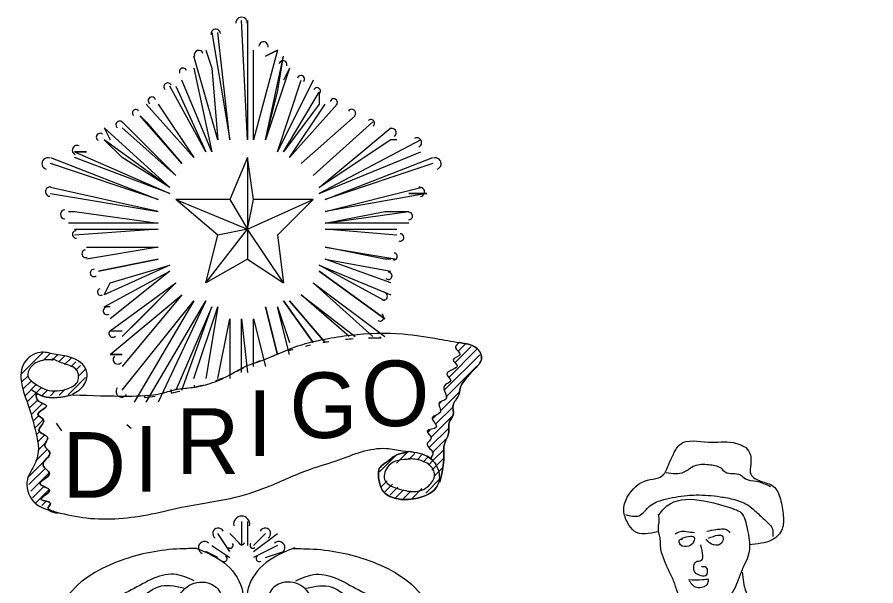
# Model space of a CAD drawing. Extents: x -1.5 to 32.9, y -63.9 to -9.8.
# Drawn here: x 14.803 to 15.935, y -13.417 to -12.666 of the extents above; entities that cross this region are included whole.
import ezdxf

# ---------------------------------------------------------------- set-up
doc = ezdxf.new("R2010")
doc.units = 0
doc.layers.add('BORDER', color=7, linetype='Continuous')

msp = doc.modelspace()

# ---------------------------------------------------------------- linework, layer by layer
at = {"layer": 'BORDER'}
for p, q in [((15.1066, -12.8281), (15.0987, -12.6706)), ((15.1066, -12.6706), (15.1066, -12.8281)), ((15.0593, -12.6864), (15.083, -12.8281)), ((15.083, -12.8281), (15.0672, -12.6864)), ((15.0515, -12.71), (15.0593, -12.7336)), ((15.1145, -12.8281), (15.1145, -12.71)), ((15.1302, -12.8281), (15.1538, -12.7179)), ((15.0357, -12.7336), (15.0593, -12.8439)), ((15.1617, -12.7336), (15.1302, -12.8281)), ((15.1617, -12.7336), (15.1538, -12.7494)), ((15.0593, -12.8439), (15.02, -12.7494)), ((15.1459, -12.8439), (15.1774, -12.7494)), ((15.0121, -12.7573), (15.0515, -12.8439)), ((15.1538, -12.8439), (15.2011, -12.7651)), ((15.02, -12.8596), (14.9648, -12.7966)), ((15.2483, -12.7966), (15.1774, -12.8596)), ((15.1932, -12.8754), (15.2719, -12.8045)), ((15.2719, -12.8045), (15.1932, -12.8754)), ((14.9176, -12.8124), (14.9255, -12.8281)), ((14.9176, -12.8124), (15.0042, -12.8911)), ((15.0121, -12.8754), (14.9412, -12.8124)), ((15.0042, -12.8911), (14.9176, -12.8281)), ((15.3349, -12.8281), (15.2011, -12.899)), ((15.3034, -12.8281), (15.2956, -12.8281)), ((14.8467, -12.8517), (14.9885, -12.9069)), ((15.0042, -12.899), (14.8782, -12.8517)), ((15.2011, -12.899), (15.3349, -12.8439)), ((15.2089, -12.9069), (15.3507, -12.8517)), ((14.9885, -12.9069), (14.8467, -12.8596)), ((15.3507, -12.8596), (15.2089, -12.9069)), ((14.9885, -12.9226), (14.8467, -12.8911)), ((15.2089, -12.9226), (15.3349, -12.8911)), ((14.8467, -12.899), (14.9885, -12.9226)), ((15.083, -12.9069), (15.1066, -12.9462)), ((15.1932, -12.9069), (15.1145, -12.9069)), ((14.8704, -12.9226), (14.8782, -12.9226)), ((15.2089, -12.9384), (15.3192, -12.9226)), ((15.3192, -12.9384), (15.2089, -12.9384)), ((15.3192, -12.9384), (15.3034, -12.9384)), ((14.9885, -12.9462), (14.8782, -12.9541)), ((14.8782, -12.9462), (14.9885, -12.9462)), ((15.0515, -13.0171), (15.0672, -12.9541)), ((15.2089, -12.9462), (15.3034, -12.9462)), ((14.894, -12.9699), (14.9885, -12.9699)), ((15.2089, -12.9699), (15.3034, -12.9856)), ((15.1066, -12.9856), (15.1538, -13.0171)), ((15.0042, -12.9935), (14.9176, -13.0328)), ((15.2877, -13.0407), (15.2011, -12.9935)), ((15.0042, -13.0014), (14.9255, -13.0643)), ((15.2011, -13.0014), (15.2877, -13.0643)), ((15.2877, -13.0643), (15.2011, -13.0014)), ((14.9255, -13.0801), (15.0121, -13.0171)), ((15.0121, -13.0171), (14.9412, -13.088)), ((15.02, -13.0328), (14.9412, -13.1273)), ((14.9412, -13.1588), (15.0357, -13.0407)), ((15.0357, -13.0407), (14.957, -13.1746)), ((15.1538, -13.0407), (15.1932, -13.0958)), ((15.1932, -13.0958), (15.1538, -13.0407)), ((15.1145, -13.0643), (15.1302, -13.1273)), ((15.1145, -13.1273), (15.1145, -13.0643)), ((14.9255, -13.0801), (14.9412, -13.0801)), ((15.3802, -13.1222), (15.4015, -13.101)), ((15.3839, -13.1074), (15.3934, -13.0979)), ((14.808, -13.1376), (14.8364, -13.1091)), ((14.8371, -13.1195), (14.8463, -13.1103)), ((14.8485, -13.1193), (14.8559, -13.1119)), ((14.858, -13.1209), (14.8651, -13.1138)), ((15.3668, -13.1579), (15.4128, -13.1119)), ((15.3719, -13.1417), (15.4095, -13.104)), ((14.8652, -13.1248), (14.8741, -13.116)), ((14.8732, -13.128), (14.8801, -13.1211)), ((14.8801, -13.1322), (14.8861, -13.1262)), ((14.8843, -13.1392), (14.8922, -13.1313)), ((15.3681, -13.1677), (15.4084, -13.1275)), ((14.809, -13.1476), (14.8167, -13.14)), ((14.8103, -13.1575), (14.8221, -13.1457)), ((14.8697, -13.1649), (14.8926, -13.142)), ((14.8131, -13.1659), (14.8278, -13.1511)), ((14.8158, -13.1742), (14.8347, -13.1553)), ((14.8351, -13.1661), (14.8427, -13.1585)), ((14.858, -13.1654), (14.8661, -13.1573)), ((14.8464, -13.1659), (14.8524, -13.1599)), ((15.3606, -13.1864), (15.3859, -13.161)), ((14.8186, -13.1826), (14.83, -13.1712)), ((14.8212, -13.1911), (14.8361, -13.1763)), ((15.354, -13.2041), (15.3776, -13.1805)), ((15.3594, -13.1765), (15.3619, -13.1739)), ((14.8235, -13.2), (14.8313, -13.1921)), ((15.3481, -13.2211), (15.3773, -13.1919)), ((15.3506, -13.1964), (15.3559, -13.1911)), ((14.8258, -13.2088), (14.8369, -13.1977)), ((14.854, -13.2024), (14.8609, -13.2123)), ((14.9473, -13.2038), (14.9532, -13.2089)), ((14.8279, -13.2178), (14.8327, -13.213)), ((14.9533, -13.209), (14.9533, -13.209)), ((15.344, -13.2141), (15.3472, -13.2109)), ((15.346, -13.2344), (15.3722, -13.2082)), ((14.8295, -13.2274), (14.8387, -13.2182)), ((14.8299, -13.2381), (14.8408, -13.2272)), ((15.35, -13.2415), (15.3689, -13.2226)), ((14.8268, -13.2523), (14.8427, -13.2364)), ((15.3514, -13.2512), (15.3657, -13.2369)), ((14.8183, -13.272), (14.8416, -13.2487)), ((15.2806, -13.2663), (15.3016, -13.2454)), ((15.3029, -13.2552), (15.3183, -13.2398)), ((15.312, -13.2417), (15.3186, -13.2397)), ((15.3186, -13.2397), (15.3126, -13.2415)), ((15.3199, -13.2493), (15.3271, -13.2421)), ((15.3309, -13.2495), (15.3358, -13.2446)), ((15.338, -13.2535), (15.3444, -13.2471)), ((15.3497, -13.2641), (15.3651, -13.2487)), ((15.345, -13.2577), (15.3514, -13.2512)), ((15.3514, -13.2512), (15.3514, -13.2512)), ((15.3528, -13.2721), (15.364, -13.2609)), ((14.8181, -13.2833), (14.8398, -13.2616)), ((14.8205, -13.292), (14.8446, -13.268)), ((15.2828, -13.2864), (15.2907, -13.2785)), ((15.2875, -13.2928), (15.2977, -13.2826)), ((15.3415, -13.2946), (15.3611, -13.275)), ((14.823, -13.3007), (14.8378, -13.2858)), ((14.8274, -13.3074), (14.8445, -13.2904)), ((15.2945, -13.297), (15.3047, -13.2868)), ((15.3014, -13.3012), (15.3123, -13.2904)), ((15.3123, -13.3015), (15.3222, -13.2916)), ((15.3234, -13.3015), (15.3364, -13.2885)), ((14.835, -13.311), (14.8404, -13.3056)), ((14.8426, -13.3145), (14.8439, -13.3132)), ((14.8502, -13.3181), (14.8504, -13.3178)), ((15.0987, -13.3321), (15.0987, -13.3636)), ((15.1066, -13.3321), (15.1066, -13.3636)), ((15.083, -13.3714), (15.0672, -13.3478)), ((15.083, -13.3478), (15.0987, -13.3636)), ((15.1302, -13.3478), (15.1145, -13.3636)), ((15.1145, -13.3714), (15.1459, -13.3478)), ((15.0672, -13.3793), (15.0515, -13.3714)), ((15.0593, -13.3636), (15.083, -13.3793)), ((15.1459, -13.3636), (15.1145, -13.3793)), ((15.1302, -13.3793), (15.1538, -13.3714))]:
    msp.add_line(p, q, dxfattribs=at)
for points in [[(15.1459, -12.71), (15.1302, -12.7179), (15.1459, -12.71), (15.1145, -12.8281)], [(15.0593, -12.7336), (15.0672, -12.8281), (15.0357, -12.7179)], [(15.1302, -12.8281), (15.1459, -12.7651), (15.1538, -12.7179)], [(15.1932, -12.7494), (15.1932, -12.7494), (15.1459, -12.8439)], [(15.0515, -12.8439), (15.0042, -12.7573), (15.0042, -12.7573)], [(15.2011, -12.7651), (15.2011, -12.7809), (15.1538, -12.8439)], [(15.0357, -12.8517), (14.9727, -12.7809), (14.9727, -12.7809)], [(14.9885, -12.7809), (14.9885, -12.7809), (15.0357, -12.8517)], [(15.1617, -12.8517), (15.2089, -12.7809), (15.2089, -12.7809)], [(15.2247, -12.7809), (15.2247, -12.7809), (15.1617, -12.8517)], [(14.9648, -12.7966), (14.9727, -12.8045), (15.02, -12.8596)], [(15.1774, -12.8596), (15.2483, -12.7966), (15.2483, -12.7966)], [(14.9412, -12.8045), (14.9412, -12.8045), (15.0121, -12.8754)], [(15.2956, -12.8281), (15.2011, -12.8911), (15.2956, -12.8124)], [(15.0042, -12.8911), (14.9412, -12.8517), (14.9176, -12.8281)], [(14.8782, -12.8439), (14.894, -12.8439), (14.8782, -12.8439), (15.0042, -12.899)], [(15.1066, -12.8517), (15.083, -12.9069), (15.0121, -12.9069)], [(15.1066, -12.9462), (15.1145, -12.9069), (15.1066, -12.8517), (15.1066, -12.9462)], [(15.0121, -12.9069), (15.1066, -12.9462), (15.0672, -12.9541), (15.0121, -12.9069)], [(15.1538, -13.0171), (15.1066, -12.9462), (15.1932, -12.9069), (15.1459, -12.9541), (15.1538, -13.0171)], [(15.3428, -12.899), (15.3192, -12.899), (15.3428, -12.899), (15.2089, -12.9226)], [(14.8782, -12.9226), (14.9885, -12.9384), (14.8704, -12.9384)], [(15.2089, -12.9384), (15.2877, -12.9226), (15.3192, -12.9226)], [(15.0515, -13.0171), (15.1066, -12.9462), (15.1066, -12.9856), (15.0515, -13.0171)], [(15.3034, -12.9541), (15.3034, -12.9541), (15.2089, -12.9462)], [(14.9885, -12.9699), (14.894, -12.9856), (14.894, -12.9856)], [(15.2956, -12.9856), (15.2877, -12.9856), (15.2089, -12.9699)], [(14.9885, -12.9856), (14.9097, -13.0014), (14.9097, -13.0014)], [(14.9097, -13.0014), (14.9097, -13.0014), (14.9885, -12.9856)], [(15.2089, -12.9856), (15.2956, -13.0014), (15.2956, -13.0014)], [(15.2956, -13.0171), (15.2956, -13.0171), (15.2089, -12.9856)], [(14.9176, -13.0328), (14.9255, -13.0171), (15.0042, -12.9935)], [(15.2011, -12.9935), (15.2956, -13.0328), (15.2956, -13.0328)], [(14.9255, -13.0486), (14.9176, -13.0486), (15.0042, -13.0014)], [(15.0121, -13.0171), (14.9648, -13.0643), (14.9412, -13.088)], [(15.2719, -13.088), (15.1932, -13.0171), (15.2877, -13.088)], [(14.9255, -13.1116), (14.9412, -13.1116), (14.9255, -13.1116), (15.02, -13.0328)], [(15.2404, -13.088), (15.1774, -13.0328), (15.2483, -13.088)], [(14.9727, -13.1746), (15.0515, -13.0407), (14.9885, -13.1746)], [(15.2089, -13.0958), (15.1617, -13.0407), (15.2089, -13.0958)], [(15.02, -13.1588), (15.0593, -13.0486), (15.0121, -13.1588)], [(15.0357, -13.1431), (15.0672, -13.0486), (15.0515, -13.1431)], [(15.1459, -13.1116), (15.1302, -13.0486), (15.1459, -13.1116)], [(15.1617, -13.1116), (15.1459, -13.0486), (15.1617, -13.0958)], [(15.0672, -13.1431), (15.083, -13.0643), (15.083, -13.1431)], [(15.0987, -13.1352), (15.0987, -13.0643), (15.1066, -13.1352)]]:
    msp.add_lwpolyline(points, dxfattribs=at)
for centre, radius, start, end in [((15.0986, -12.6738), 0.00755, 357.1826, 182.8173), ((15.0645, -12.6884), 0.00619, 5.393, 191.7646), ((15.1276, -12.705), 0.00619, 350.1804, 175.8995), ((15.042, -12.716), 0.00582, 17.376, 196.8363), ((15.1532, -12.7289), 0.00511, 342.8963, 168.4542), ((15.1532, -12.7289), 0.00511, 342.8963, 168.4542), ((15.0214, -12.7383), 0.00489, 17.9645, 203.4061), ((15.1768, -12.7482), 0.00486, 320.8089, 162.7274), ((15.0011, -12.7582), 0.00511, 70.3448, 221.3241), ((15.001, -12.7582), 0.00511, 24.7411, 69.1068), ((15.1981, -12.7638), 0.0045, 323.156, 155.8564), ((14.9802, -12.7764), 0.00486, 13.5339, 237.5514), ((15.2202, -12.7788), 0.00486, 301.5339, 165.5514), ((14.9592, -12.7928), 0.0045, 35.156, 227.8564), ((15.2439, -12.793), 0.00511, 358.3448, 149.3241), ((15.244, -12.7929), 0.00511, 312.7411, 357.1068), ((14.9377, -12.8082), 0.00486, 32.8089, 234.7274), ((15.2692, -12.8062), 0.00489, 305.9645, 131.4061), ((14.9121, -12.8247), 0.00511, 54.8963, 240.4542), ((14.9121, -12.8247), 0.00511, 54.8963, 240.4542), ((15.2968, -12.8189), 0.00582, 305.376, 124.8363), ((15.3299, -12.8317), 0.00619, 293.393, 119.7646), ((14.8815, -12.8417), 0.00619, 62.1804, 247.8995), ((14.8429, -12.8596), 0.00755, 69.1826, 254.8173), ((15.3544, -12.8596), 0.00755, 285.1826, 110.8173), ((14.8462, -12.8966), 0.00619, 77.393, 263.7646), ((15.3337, -12.8969), 0.00619, 278.1804, 103.8995), ((14.8655, -12.9265), 0.00582, 89.376, 268.8363), ((15.3189, -12.9286), 0.00511, 270.8963, 96.4542), ((15.3189, -12.9286), 0.00511, 270.8963, 96.4542), ((14.8804, -12.953), 0.00489, 89.9645, 275.4061), ((15.3078, -12.957), 0.00486, 248.8089, 90.7274), ((14.893, -12.9785), 0.00511, 142.3448, 293.3241), ((14.893, -12.9785), 0.00511, 96.7411, 141.1068), ((15.2995, -12.9821), 0.0045, 251.156, 83.8564), ((14.9039, -13.0039), 0.00486, 85.5339, 309.5514), ((15.2922, -13.0077), 0.00486, 229.5339, 93.5514), ((14.913, -13.029), 0.0045, 107.156, 299.8564), ((15.2859, -13.0347), 0.00511, 286.3448, 77.3241), ((15.286, -13.0346), 0.00511, 240.7411, 285.1068), ((14.921, -13.0542), 0.00486, 104.8089, 306.7274), ((15.2812, -13.0627), 0.00489, 233.9645, 59.4061), ((14.9287, -13.0837), 0.00511, 126.8963, 312.4542), ((14.9287, -13.0837), 0.00511, 126.8963, 312.4542), ((15.2776, -13.4999), 0.4101, 94.476, 95.8869), ((15.2776, -13.4999), 0.4101, 89.309, 91.6378), ((15.2777, -13.0929), 0.00582, 32.6325, 52.8363), ((15.2776, -13.4999), 0.4101, 102.4333, 103.3721), ((15.2776, -13.4999), 0.4101, 98.9754, 100.1027), ((14.9354, -13.118), 0.00619, 134.1804, 319.8995), ((15.2811, -13.4987), 0.4101, 109.4777, 110.3523), ((15.2776, -13.4999), 0.4101, 105.7463, 106.5669), ((15.2776, -13.4999), 0.4101, 112.0958, 113.0399), ((15.2776, -13.4999), 0.4101, 115.5498, 116.8156), ((14.9104, -12.7094), 0.463, 289.4479, 290.8028), ((14.9406, -13.1603), 0.00755, 141.1826, 326.8173), ((15.0111, -13.1594), 0.00582, 161.376, 210.7093), ((15.0409, -13.1534), 0.00489, 161.9645, 198.0036), ((14.9104, -12.7094), 0.463, 285.7687, 287.057), ((14.9767, -13.1685), 0.00619, 149.393, 179.6336), ((14.9104, -12.7094), 0.463, 277.4585, 279.219), ((14.9104, -12.7094), 0.463, 281.9281, 283.3221), ((15.0987, -13.3354), 0.0106, 90, 191.5759), ((15.0987, -13.3354), 0.0106, 348.4241, 90), ((15.0678, -13.3479), 0.00729, 27.483, 235.1773), ((15.1296, -13.3479), 0.00729, 304.8227, 152.517), ((15.0497, -13.3665), 0.00808, 47.6012, 249.1306), ((15.0837, -13.3635), 0.00385, 229.0097, 37.0846), ((15.0987, -13.3585), 0.00409, 196.3263, 270), ((15.0987, -13.3585), 0.00409, 270, 343.6737), ((15.1136, -13.3635), 0.00385, 142.9154, 310.9903), ((15.1477, -13.3665), 0.00808, 290.8694, 132.3988), ((15.0755, -13.3808), 0.00417, 238.0162, 57.3654), ((15.1219, -13.3808), 0.00417, 122.6346, 301.9838)]:
    msp.add_arc(centre, radius, start, end, dxfattribs=at)
for points in [[(14.8765, -13.1649), (14.9484, -13.1664), (14.9936, -13.1626), (15.0142, -13.1573), (15.0341, -13.155), (15.0571, -13.1497), (15.0823, -13.139), (15.1014, -13.1284), (15.1259, -13.1193), (15.168, -13.1019), (15.2085, -13.0912), (15.2422, -13.0859), (15.3118, -13.0844), (15.3592, -13.0912), (15.3898, -13.0965), (15.4097, -13.1041), (15.4151, -13.1178), (15.4066, -13.1299), (15.3959, -13.1421), (15.3868, -13.1565), (15.3852, -13.1649), (15.3776, -13.1785), (15.3776, -13.1914), (15.373, -13.1998), (15.3715, -13.2157), (15.3661, -13.2301), (15.3653, -13.243), (15.3646, -13.2582), (15.36, -13.2802)], [(15.386, -13.0958), (15.3806, -13.1026), (15.3868, -13.1117), (15.3776, -13.1186), (15.3829, -13.1261), (15.3692, -13.1375), (15.3745, -13.1459), (15.3661, -13.1527), (15.3684, -13.1702), (15.3592, -13.1755), (15.3608, -13.1876), (15.35, -13.1952), (15.3554, -13.2074), (15.3432, -13.2127), (15.3485, -13.2218), (15.3432, -13.2294), (15.3508, -13.243), (15.3485, -13.2484), (15.3516, -13.2514)], [(15.386, -13.0958), (15.3806, -13.1026), (15.3868, -13.1117), (15.3776, -13.1186), (15.3829, -13.1261), (15.3692, -13.1375), (15.3745, -13.1459), (15.3661, -13.1527), (15.3684, -13.1702), (15.3592, -13.1755), (15.3608, -13.1876), (15.35, -13.1952), (15.3554, -13.2074), (15.3432, -13.2127), (15.3485, -13.2218), (15.3432, -13.2294), (15.3508, -13.243), (15.3485, -13.2484), (15.3516, -13.2514)], [(15.36, -13.2802), (15.3646, -13.2582), (15.3653, -13.243), (15.3661, -13.2301), (15.3715, -13.2157), (15.373, -13.1998), (15.3776, -13.1914), (15.3776, -13.1785), (15.3852, -13.1649), (15.3868, -13.1565), (15.3959, -13.1421), (15.4066, -13.1299), (15.4151, -13.1178), (15.4097, -13.1041), (15.3898, -13.0965), (15.386, -13.0958)], [(14.8758, -13.1641), (14.8911, -13.1512), (14.8941, -13.133), (14.8735, -13.1155), (14.8513, -13.111), (14.8329, -13.1087), (14.8123, -13.1223), (14.8077, -13.1353), (14.81, -13.1565), (14.8207, -13.1891), (14.8276, -13.2157), (14.8306, -13.2347), (14.8261, -13.2559), (14.8161, -13.2764), (14.8245, -13.306), (14.8544, -13.3197), (14.8941, -13.3273), (14.9798, -13.322), (15.0249, -13.3121), (15.0838, -13.3015), (15.1328, -13.2863), (15.1894, -13.2628), (15.2269, -13.2506), (15.2567, -13.24), (15.2896, -13.2355), (15.311, -13.2385), (15.3462, -13.2476), (15.3592, -13.2689), (15.3554, -13.2871), (15.3286, -13.3015), (15.3019, -13.3015), (15.2843, -13.2909), (15.2797, -13.2764), (15.2812, -13.2605), (15.2911, -13.2529), (15.2996, -13.2461), (15.3126, -13.2415)], [(14.8758, -13.1641), (14.8911, -13.1512), (14.8941, -13.133), (14.8735, -13.1155), (14.8513, -13.111), (14.8329, -13.1087), (14.8123, -13.1223), (14.8077, -13.1353), (14.81, -13.1565), (14.8207, -13.1891), (14.8276, -13.2157), (14.8306, -13.2347), (14.8261, -13.2559), (14.8161, -13.2764), (14.8245, -13.306), (14.8528, -13.3193)], [(14.8505, -13.1186), (14.836, -13.1193), (14.8199, -13.1292), (14.8169, -13.1398), (14.8291, -13.152), (14.8414, -13.158), (14.8697, -13.1565), (14.8827, -13.1466), (14.8811, -13.1322), (14.8651, -13.1239), (14.8494, -13.1174)], [(14.877, -13.1646), (14.836, -13.1664), (14.8222, -13.1588)], [(14.8276, -13.1633), (14.8306, -13.1732), (14.8414, -13.1793), (14.8299, -13.1907), (14.8375, -13.1983), (14.8314, -13.2119), (14.8429, -13.2218), (14.8391, -13.2317), (14.8459, -13.2408), (14.8368, -13.2575), (14.8452, -13.2689), (14.8329, -13.2825), (14.8452, -13.2909), (14.8345, -13.303), (14.8467, -13.3083), (14.8436, -13.3136), (14.8559, -13.3212)], [(14.8528, -13.3193), (14.8436, -13.3136), (14.8467, -13.3083), (14.8345, -13.303), (14.8452, -13.2909), (14.8329, -13.2825), (14.8452, -13.2689), (14.8368, -13.2575), (14.8459, -13.2408), (14.8391, -13.2317), (14.8429, -13.2218), (14.8314, -13.2119), (14.8375, -13.1983), (14.8299, -13.1907), (14.8414, -13.1793), (14.8306, -13.1732), (14.8276, -13.1633)], [(14.828, -13.1628), (14.836, -13.1664), (14.8758, -13.1647)], [(15.6478, -13.3456), (15.6165, -13.3448), (15.6081, -13.3342), (15.6027, -13.3175), (15.6073, -13.3), (15.6341, -13.2773), (15.6486, -13.2742), (15.6555, -13.2697), (15.6593, -13.2628), (15.6685, -13.2423), (15.6769, -13.2302), (15.7144, -13.2272), (15.7473, -13.2279), (15.7672, -13.2385), (15.7702, -13.256), (15.7702, -13.2697), (15.7832, -13.2788), (15.8001, -13.2856), (15.8092, -13.3023), (15.8131, -13.3243), (15.8115, -13.3418), (15.7985, -13.3562), (15.784, -13.3608), (15.7679, -13.363)], [(15.3126, -13.2415), (15.2996, -13.2461), (15.2911, -13.2529), (15.2812, -13.2605), (15.2797, -13.2764), (15.2843, -13.2909), (15.3019, -13.3015), (15.3286, -13.3015), (15.3554, -13.2871), (15.3592, -13.28)], [(15.321, -13.2499), (15.2927, -13.2582), (15.2873, -13.2764), (15.3103, -13.2901), (15.3286, -13.2924), (15.347, -13.2833), (15.3531, -13.2689), (15.3432, -13.2552), (15.3271, -13.2499), (15.3183, -13.2492)], [(15.3513, -13.2517), (15.3462, -13.2476), (15.3186, -13.2397)], [(15.6586, -13.2674), (15.6823, -13.2666), (15.696, -13.2583), (15.7144, -13.2568), (15.7305, -13.2613), (15.7366, -13.2666), (15.7565, -13.2704), (15.7633, -13.2757), (15.7779, -13.2788), (15.7871, -13.2818), (15.7962, -13.2856)], [(15.6494, -13.3228), (15.6555, -13.3152), (15.748, -13.3152)], [(15.605, -13.3228), (15.6226, -13.3243), (15.6371, -13.3114), (15.6555, -13.3031), (15.6861, -13.2977), (15.6983, -13.297), (15.7297, -13.2993), (15.7488, -13.3031), (15.7679, -13.3114), (15.7802, -13.322), (15.7932, -13.3342), (15.7985, -13.341), (15.7993, -13.3516)], [(15.7465, -13.3152), (15.7557, -13.319), (15.7649, -13.3387), (15.7664, -13.3782), (15.7611, -13.3904), (15.7549, -13.4055), (15.7419, -13.4313), (15.7266, -13.4435), (15.7106, -13.4503), (15.6914, -13.4503), (15.6731, -13.4238), (15.6677, -13.4086), (15.6608, -13.3942), (15.6563, -13.3835), (15.6517, -13.3691), (15.6501, -13.3516), (15.6486, -13.3456), (15.6494, -13.3289), (15.6486, -13.3221)], [(15.696, -13.3471), (15.6853, -13.3456), (15.6769, -13.3456), (15.67, -13.3486)], [(15.6792, -13.3539), (15.696, -13.3539), (15.6945, -13.3592), (15.6884, -13.3645), (15.6777, -13.363), (15.6761, -13.36), (15.6761, -13.3562), (15.68, -13.3554)], [(15.7144, -13.3539), (15.7335, -13.3524), (15.732, -13.36), (15.7213, -13.363), (15.7113, -13.3554)], [(15.7121, -13.3448), (15.7243, -13.3425), (15.732, -13.3418), (15.7381, -13.3425), (15.7427, -13.3471)], [(15.7037, -13.363), (15.7029, -13.3843), (15.6991, -13.385), (15.696, -13.3873), (15.6945, -13.3942), (15.696, -13.3987), (15.6991, -13.401), (15.7022, -13.4025), (15.7106, -13.4033), (15.7129, -13.3949), (15.7113, -13.3926), (15.7052, -13.3919)], [(15.0396, -13.3678), (15.0178, -13.3681), (14.9396, -13.3835), (14.8684, -13.4312), (14.8251, -13.4971), (14.7426, -13.5336), (14.7119, -13.5448), (14.7007, -13.5153), (14.7119, -13.5083), (14.7189, -13.5195), (14.7287, -13.5251), (14.7357, -13.5167), (14.7412, -13.5041), (14.7399, -13.4873), (14.7161, -13.4789), (14.6965, -13.4859), (14.6882, -13.4943), (14.6812, -13.5125), (14.6784, -13.535), (14.6868, -13.563), (14.7091, -13.5967), (14.7538, -13.671), (14.7678, -13.6976), (14.779, -13.7187), (14.7846, -13.7678), (14.7776, -13.8056), (14.7664, -13.8323), (14.7454, -13.8561), (14.7105, -13.8785), (14.691, -13.8828), (14.6798, -13.8771), (14.6644, -13.8603), (14.6574, -13.8463), (14.6602, -13.8393), (14.6714, -13.8393), (14.677, -13.8477), (14.6798, -13.8575), (14.6882, -13.8617), (14.7007, -13.8589), (14.7007, -13.8533), (14.7007, -13.8365), (14.6924, -13.8267), (14.6784, -13.8224), (14.6714, -13.821), (14.6658, -13.821), (14.6602, -13.8267), (14.6532, -13.8379), (14.6477, -13.8505), (14.6449, -13.8645), (14.6449, -13.8729), (14.6519, -13.8842), (14.6616, -13.8912), (14.6672, -13.894), (14.6826, -13.894), (14.691, -13.8954)], [(15.0374, -13.3667), (15.0751, -13.3863), (15.0988, -13.42), (15.0988, -13.4522), (15.0849, -13.4803), (15.0514, -13.4859), (15.0206, -13.4648), (15.0136, -13.4396), (15.0262, -13.4186), (15.0541, -13.413), (15.0695, -13.4242), (15.0723, -13.4312)], [(15.1688, -13.3667), (15.131, -13.3863), (15.1073, -13.42), (15.1073, -13.4522), (15.1213, -13.4803), (15.1548, -13.4859), (15.1855, -13.4648), (15.1925, -13.4396), (15.1799, -13.4186), (15.152, -13.413), (15.1366, -13.4242), (15.1338, -13.4312)], [(15.1665, -13.3678), (15.1883, -13.3681), (15.2665, -13.3835), (15.3378, -13.4312), (15.3811, -13.4971), (15.4635, -13.5336), (15.4942, -13.5448), (15.5054, -13.5153), (15.4942, -13.5083), (15.4872, -13.5195), (15.4775, -13.5251), (15.4705, -13.5167), (15.4649, -13.5041), (15.4663, -13.4873), (15.49, -13.4789), (15.5096, -13.4859), (15.518, -13.4943), (15.525, -13.5125), (15.5278, -13.535), (15.5194, -13.563), (15.497, -13.5967), (15.4523, -13.671), (15.4384, -13.6976), (15.4272, -13.7187), (15.4216, -13.7678), (15.4286, -13.8056), (15.4397, -13.8323), (15.4607, -13.8561), (15.4956, -13.8785), (15.5152, -13.8828), (15.5264, -13.8771), (15.5417, -13.8603), (15.5487, -13.8463), (15.5459, -13.8393), (15.5347, -13.8393), (15.5291, -13.8477), (15.5264, -13.8575), (15.518, -13.8617), (15.5054, -13.8589), (15.5054, -13.8533), (15.5054, -13.8365), (15.5138, -13.8267), (15.5278, -13.8224), (15.5347, -13.821), (15.5403, -13.821), (15.5459, -13.8267), (15.5529, -13.8379), (15.5585, -13.8505), (15.5613, -13.8645), (15.5613, -13.8729), (15.5543, -13.8842), (15.5445, -13.8912), (15.5389, -13.894), (15.5236, -13.894), (15.5152, -13.8954)], [(15.036, -13.4101), (15.0094, -13.4017), (14.9494, -13.4242), (14.92, -13.4396), (14.9061, -13.4522)], [(15.1702, -13.4101), (15.1967, -13.4017), (15.2568, -13.4242), (15.2861, -13.4396), (15.3001, -13.4522)], [(15.688, -13.4087), (15.7067, -13.4086), (15.7144, -13.4078)], [(15.7588, -13.3987), (15.7641, -13.4252), (15.771, -13.4366), (15.7878, -13.4473), (15.8001, -13.4526), (15.8169, -13.4503), (15.8337, -13.4518), (15.8483, -13.4556), (15.8651, -13.4579), (15.8865, -13.4753), (15.8903, -13.4905), (15.9003, -13.5801), (15.9209, -13.6249), (15.9309, -13.6674), (15.9278, -13.7099), (15.8942, -13.7281), (15.8276, -13.7532), (15.7962, -13.7615), (15.7832, -13.7668), (15.7779, -13.76), (15.7702, -13.7387), (15.7641, -13.7236), (15.7611, -13.7122), (15.7764, -13.7), (15.7832, -13.6917), (15.8337, -13.6583), (15.8383, -13.6294), (15.836, -13.5968), (15.8383, -13.5824), (15.8444, -13.5846), (15.849, -13.5998), (15.8452, -13.6378), (15.8429, -13.6575), (15.8353, -13.6651), (15.8307, -13.6651)], [(15.022, -13.42), (14.9885, -13.4186), (14.962, -13.4354), (14.9326, -13.4466), (14.9075, -13.4536), (14.9047, -13.4522)], [(15.1841, -13.42), (15.2176, -13.4186), (15.2442, -13.4354), (15.2735, -13.4466), (15.2987, -13.4536), (15.3015, -13.4522)], [(15.6891, -13.4101), (15.6937, -13.4162), (15.709, -13.4177), (15.7129, -13.4146), (15.7144, -13.4086)]]:
    msp.add_spline(points, degree=3, dxfattribs=at)

# ---------------------------------------------------------------- texts
for s, p in [('O', (15.2562, -13.2061)), ('G', (15.1617, -13.2218)), ('I', (15.1066, -13.2454)), ('R', (15.0121, -13.2691)), ('D', (14.8625, -13.3006)), ('I', (14.957, -13.2927))]:
    msp.add_text(s, height=0.0866, dxfattribs=at).set_placement(p)

doc.saveas('drawing.dxf')
